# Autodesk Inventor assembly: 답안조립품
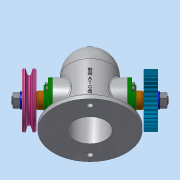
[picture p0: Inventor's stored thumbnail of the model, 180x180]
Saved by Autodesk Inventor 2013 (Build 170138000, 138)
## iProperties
Created: 2019-11
Part Number: 답안조립품
Document SubType Name: Assembly
Designer: Administrator
Author: Administrator
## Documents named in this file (14)
- C:\Users\Administrator\Desktop\491104V1057\답안조립품.iam
- C:\Users\Administrator\Desktop\491104V1057\V-벨트풀리.ipt
- V-벨트풀리.ipt
- C:\Users\Administrator\Desktop\491104V1057\너트 M12x1.25.ipt
- C:\Users\Administrator\Desktop\491104V1057\베어링 6203.ipt
- C:\Users\Administrator\Desktop\491104V1057\본체.ipt
- C:\Users\Administrator\Desktop\491104V1057\볼트 M4.ipt
- C:\Users\Administrator\Desktop\491104V1057\부시.ipt
- C:\Users\Administrator\Desktop\491104V1057\스퍼기어.ipt
- C:\Users\Administrator\Desktop\491104V1057\오일 실 26 38 8.ipt
- C:\Users\Administrator\Desktop\491104V1057\와셔 12x24.ipt
- C:\Users\Administrator\Desktop\491104V1057\축.ipt
- C:\Users\Administrator\Desktop\491104V1057\커버.ipt
- C:\Users\Administrator\Desktop\491104V1057\키 5x5x12.ipt
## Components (1 placed, 1 different names)
1. V-벨트풀리:1
